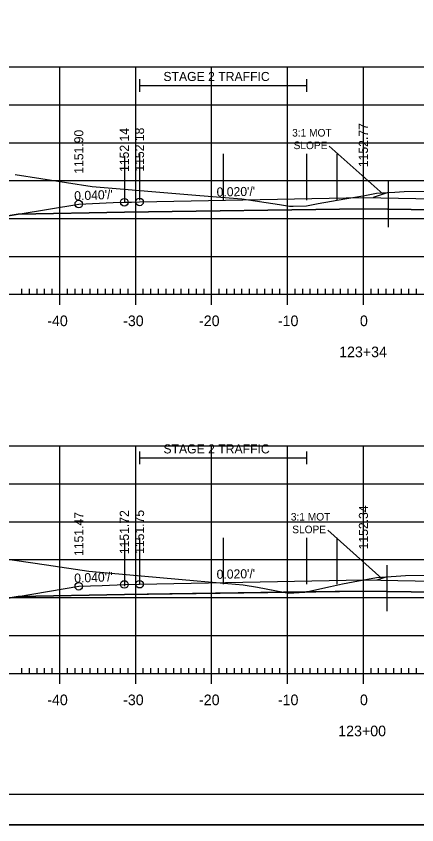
# Model space of a CAD drawing. Extents: x 1322838 to 1324533, y 339903 to 351025.
# Drawn here: x 1323658 to 1323710.8, y 341183.1 to 341289.8 of the extents above; entities that cross this region are included whole.
import ezdxf

# ---------------------------------------------------------------- set-up
doc = ezdxf.new("R2010")
doc.units = 0
for name, color, linetype in [('R_Alt Surface', 7, 'Continuous'), ('R_Axis', 7, 'Continuous'), ('R_Axis Annot', 7, 'Continuous'), ('R_Border', 7, 'Continuous'), ('R_Exist Surface', 7, 'Continuous'), ('R_Fin Surface', 7, 'Continuous'), ('R_Fin Surface Annot', 7, 'Continuous'), ('R_Grid', 7, 'Continuous'), ('R_MOT', 7, 'Continuous'), ('R_No Plot', 7, 'Continuous')]:
    doc.layers.add(name, color=color, linetype=linetype)

msp = doc.modelspace()

# ---------------------------------------------------------------- linework, layer by layer
at = {"layer": 'R_Alt Surface'}
for points in [[(1323658.22, 341263.7), (1323672.22, 341263.98), (1323703.71, 341264.4), (1323735.21, 341263.98), (1323749.21, 341263.7)], [(1323658.22, 341213.27), (1323672.22, 341213.55), (1323703.72, 341213.98), (1323735.22, 341213.55), (1323749.21, 341213.27)]]:
    msp.add_lwpolyline(points, dxfattribs=at)
at = {"layer": 'R_Axis'}
for p, q in [((1323658.72, 341253.13), (1323658.72, 341253.83)), ((1323659.72, 341253.13), (1323659.72, 341253.83)), ((1323660.72, 341253.13), (1323660.72, 341253.83)), ((1323661.72, 341253.13), (1323661.72, 341253.83)), ((1323662.72, 341253.13), (1323662.72, 341253.83)), ((1323663.72, 341251.73), (1323663.72, 341254.53)), ((1323664.72, 341253.13), (1323664.72, 341253.83)), ((1323665.72, 341253.13), (1323665.72, 341253.83)), ((1323666.72, 341253.13), (1323666.72, 341253.83)), ((1323667.72, 341253.13), (1323667.72, 341253.83)), ((1323668.72, 341253.13), (1323668.72, 341253.83)), ((1323669.72, 341253.13), (1323669.72, 341253.83)), ((1323670.72, 341253.13), (1323670.72, 341253.83)), ((1323671.72, 341253.13), (1323671.72, 341253.83)), ((1323672.72, 341253.13), (1323672.72, 341253.83)), ((1323673.72, 341251.73), (1323673.72, 341254.53)), ((1323674.72, 341253.13), (1323674.72, 341253.83)), ((1323675.72, 341253.13), (1323675.72, 341253.83)), ((1323676.72, 341253.13), (1323676.72, 341253.83)), ((1323677.72, 341253.13), (1323677.72, 341253.83)), ((1323678.72, 341253.13), (1323678.72, 341253.83)), ((1323679.72, 341253.13), (1323679.72, 341253.83)), ((1323680.72, 341253.13), (1323680.72, 341253.83)), ((1323681.72, 341253.13), (1323681.72, 341253.83)), ((1323682.72, 341253.13), (1323682.72, 341253.83)), ((1323683.72, 341251.73), (1323683.72, 341254.53)), ((1323684.72, 341253.13), (1323684.72, 341253.83)), ((1323685.72, 341253.13), (1323685.72, 341253.83)), ((1323686.72, 341253.13), (1323686.72, 341253.83)), ((1323687.72, 341253.13), (1323687.72, 341253.83)), ((1323688.72, 341253.13), (1323688.72, 341253.83)), ((1323689.72, 341253.13), (1323689.72, 341253.83)), ((1323690.72, 341253.13), (1323690.72, 341253.83)), ((1323691.72, 341253.13), (1323691.72, 341253.83)), ((1323692.72, 341253.13), (1323692.72, 341253.83)), ((1323693.72, 341251.73), (1323693.72, 341254.53)), ((1323694.72, 341253.13), (1323694.72, 341253.83)), ((1323695.72, 341253.13), (1323695.72, 341253.83)), ((1323696.72, 341253.13), (1323696.72, 341253.83)), ((1323697.72, 341253.13), (1323697.72, 341253.83)), ((1323698.72, 341253.13), (1323698.72, 341253.83)), ((1323699.72, 341253.13), (1323699.72, 341253.83)), ((1323700.72, 341253.13), (1323700.72, 341253.83)), ((1323701.72, 341253.13), (1323701.72, 341253.83)), ((1323702.72, 341253.13), (1323702.72, 341253.83)), ((1323703.72, 341251.73), (1323703.72, 341254.53)), ((1323704.72, 341253.13), (1323704.72, 341253.83)), ((1323705.72, 341253.13), (1323705.72, 341253.83)), ((1323706.72, 341253.13), (1323706.72, 341253.83)), ((1323707.72, 341253.13), (1323707.72, 341253.83)), ((1323708.72, 341253.13), (1323708.72, 341253.83)), ((1323709.72, 341253.13), (1323709.72, 341253.83)), ((1323710.72, 341253.13), (1323710.72, 341253.83)), ((1323563.72, 341253.13), (1323843.72, 341253.13)), ((1323658.72, 341203.13), (1323658.72, 341203.83)), ((1323659.72, 341203.13), (1323659.72, 341203.83)), ((1323660.72, 341203.13), (1323660.72, 341203.83)), ((1323661.72, 341203.13), (1323661.72, 341203.83)), ((1323662.72, 341203.13), (1323662.72, 341203.83)), ((1323663.72, 341201.73), (1323663.72, 341204.53)), ((1323664.72, 341203.13), (1323664.72, 341203.83)), ((1323665.72, 341203.13), (1323665.72, 341203.83)), ((1323666.72, 341203.13), (1323666.72, 341203.83)), ((1323667.72, 341203.13), (1323667.72, 341203.83)), ((1323668.72, 341203.13), (1323668.72, 341203.83)), ((1323669.72, 341203.13), (1323669.72, 341203.83)), ((1323670.72, 341203.13), (1323670.72, 341203.83)), ((1323671.72, 341203.13), (1323671.72, 341203.83)), ((1323672.72, 341203.13), (1323672.72, 341203.83)), ((1323673.72, 341201.73), (1323673.72, 341204.53)), ((1323674.72, 341203.13), (1323674.72, 341203.83)), ((1323675.72, 341203.13), (1323675.72, 341203.83)), ((1323676.72, 341203.13), (1323676.72, 341203.83)), ((1323677.72, 341203.13), (1323677.72, 341203.83)), ((1323678.72, 341203.13), (1323678.72, 341203.83)), ((1323679.72, 341203.13), (1323679.72, 341203.83)), ((1323680.72, 341203.13), (1323680.72, 341203.83)), ((1323681.72, 341203.13), (1323681.72, 341203.83)), ((1323682.72, 341203.13), (1323682.72, 341203.83)), ((1323683.72, 341201.73), (1323683.72, 341204.53)), ((1323684.72, 341203.13), (1323684.72, 341203.83)), ((1323685.72, 341203.13), (1323685.72, 341203.83)), ((1323686.72, 341203.13), (1323686.72, 341203.83)), ((1323687.72, 341203.13), (1323687.72, 341203.83)), ((1323688.72, 341203.13), (1323688.72, 341203.83)), ((1323689.72, 341203.13), (1323689.72, 341203.83)), ((1323690.72, 341203.13), (1323690.72, 341203.83)), ((1323691.72, 341203.13), (1323691.72, 341203.83)), ((1323692.72, 341203.13), (1323692.72, 341203.83)), ((1323693.72, 341201.73), (1323693.72, 341204.53)), ((1323694.72, 341203.13), (1323694.72, 341203.83)), ((1323695.72, 341203.13), (1323695.72, 341203.83)), ((1323696.72, 341203.13), (1323696.72, 341203.83)), ((1323697.72, 341203.13), (1323697.72, 341203.83)), ((1323698.72, 341203.13), (1323698.72, 341203.83)), ((1323699.72, 341203.13), (1323699.72, 341203.83)), ((1323700.72, 341203.13), (1323700.72, 341203.83)), ((1323701.72, 341203.13), (1323701.72, 341203.83)), ((1323702.72, 341203.13), (1323702.72, 341203.83)), ((1323703.72, 341201.73), (1323703.72, 341204.53)), ((1323704.72, 341203.13), (1323704.72, 341203.83)), ((1323705.72, 341203.13), (1323705.72, 341203.83)), ((1323706.72, 341203.13), (1323706.72, 341203.83)), ((1323707.72, 341203.13), (1323707.72, 341203.83)), ((1323708.72, 341203.13), (1323708.72, 341203.83)), ((1323709.72, 341203.13), (1323709.72, 341203.83)), ((1323710.72, 341203.13), (1323710.72, 341203.83)), ((1323563.72, 341203.13), (1323843.72, 341203.13))]:
    msp.add_line(p, q, dxfattribs=at)
at = {"layer": 'R_Axis Annot'}
for p, q in [((1323674.22, 341281.52), (1323674.22, 341279.82)), ((1323696.22, 341281.52), (1323696.22, 341279.82)), ((1323674.22, 341280.67), (1323696.22, 341280.67)), ((1323674.22, 341232.41), (1323674.22, 341230.7)), ((1323674.22, 341231.55), (1323696.22, 341231.55)), ((1323696.22, 341232.41), (1323696.22, 341230.7))]:
    msp.add_line(p, q, dxfattribs=at)
at = {"layer": 'R_Border'}
msp.add_line((1323861.9, 341187.13), (1323545.72, 341187.13), dxfattribs=at)
at = {"layer": 'R_Exist Surface'}
for points in [[(1323657.83, 341268.91), (1323667.97, 341267.35), (1323682.17, 341266.18), (1323687.68, 341265.72), (1323692.67, 341264.96), (1323693.99, 341264.74), (1323694.46, 341264.76), (1323696.22, 341264.8), (1323697.75, 341265.09), (1323701.25, 341265.72), (1323703.92, 341266.18), (1323705.45, 341266.46), (1323707.86, 341266.62), (1323709.1, 341266.7), (1323713.35, 341266.74)], [(1323653.2, 341218.73), (1323661.95, 341217.43), (1323667.55, 341216.59), (1323681.82, 341215.34), (1323687.89, 341214.82), (1323689.75, 341214.49), (1323693.83, 341213.71), (1323695.27, 341213.79), (1323696.02, 341213.83), (1323699.39, 341214.59), (1323700.98, 341214.93), (1323702.37, 341215.19), (1323705.45, 341215.78), (1323708.03, 341215.96), (1323709.28, 341216.04), (1323713.52, 341216.08)]]:
    msp.add_lwpolyline(points, dxfattribs=at)
at = {"layer": 'R_Fin Surface'}
for points in [[(1323613.69, 341271.54), (1323644.22, 341261.37), (1323658.22, 341263.7), (1323658.23, 341263.7), (1323666.22, 341265.03), (1323670.76, 341265.22), (1323672.22, 341265.27), (1323673.18, 341265.29), (1323674.22, 341265.31), (1323703.72, 341265.9), (1323715.25, 341265.67), (1323733.21, 341265.31), (1323733.22, 341265.31), (1323735.22, 341265.27), (1323738.05, 341265.16), (1323741.22, 341265.03), (1323749.21, 341263.7), (1323752.38, 341263.17), (1323763.21, 341261.37), (1323763.22, 341261.37), (1323773.05, 341264.65)], [(1323616.14, 341220.3), (1323644.22, 341210.94), (1323658.22, 341213.27), (1323666.22, 341214.61), (1323669.31, 341214.73), (1323672.22, 341214.85), (1323674.14, 341214.88), (1323674.22, 341214.89), (1323703.72, 341215.48), (1323733.22, 341214.89), (1323734.26, 341214.86), (1323735.22, 341214.85), (1323739.03, 341214.69), (1323741.22, 341214.61), (1323749.21, 341213.27), (1323763.22, 341210.94), (1323766.99, 341212.2), (1323770.21, 341213.27)]]:
    msp.add_lwpolyline(points, dxfattribs=at)
at = {"layer": 'R_Grid'}
for p, q in [((1323563.72, 341283.13), (1323843.72, 341283.13)), ((1323663.72, 341253.13), (1323663.72, 341283.13)), ((1323673.72, 341253.13), (1323673.72, 341283.13)), ((1323683.72, 341253.13), (1323683.72, 341283.13)), ((1323693.72, 341253.13), (1323693.72, 341283.13)), ((1323703.72, 341253.13), (1323703.72, 341283.13)), ((1323563.72, 341278.13), (1323843.72, 341278.13)), ((1323563.72, 341273.13), (1323843.72, 341273.13)), ((1323563.72, 341268.13), (1323843.72, 341268.13)), ((1323563.72, 341263.13), (1323843.72, 341263.13)), ((1323563.72, 341258.13), (1323843.72, 341258.13)), ((1323563.72, 341253.13), (1323843.72, 341253.13)), ((1323563.72, 341233.13), (1323843.72, 341233.13)), ((1323663.72, 341203.13), (1323663.72, 341233.13)), ((1323673.72, 341203.13), (1323673.72, 341233.13)), ((1323683.72, 341203.13), (1323683.72, 341233.13)), ((1323693.72, 341203.13), (1323693.72, 341233.13)), ((1323703.72, 341203.13), (1323703.72, 341233.13)), ((1323563.72, 341228.13), (1323843.72, 341228.13)), ((1323563.72, 341223.13), (1323843.72, 341223.13)), ((1323563.72, 341218.13), (1323843.72, 341218.13)), ((1323563.72, 341213.13), (1323843.72, 341213.13)), ((1323563.72, 341208.13), (1323843.72, 341208.13)), ((1323563.72, 341203.13), (1323843.72, 341203.13))]:
    msp.add_line(p, q, dxfattribs=at)
at = {"layer": 'R_MOT'}
for p, q in [((1323706.32, 341266.32), (1323699.22, 341272.68)), ((1323706.97, 341266.54), (1323704.99, 341265.88)), ((1323706.14, 341215.66), (1323699.04, 341222.02)), ((1323706.79, 341215.87), (1323705.5, 341215.44))]:
    msp.add_line(p, q, dxfattribs=at)
at = {"layer": 'R_No Plot'}
for p, q in [((1323672.22, 341271.38), (1323672.22, 341265.27)), ((1323674.22, 341271.64), (1323674.22, 341265.53)), ((1323685.22, 341271.64), (1323685.22, 341265.53)), ((1323696.22, 341271.64), (1323696.22, 341265.53)), ((1323700.22, 341271.64), (1323700.22, 341265.53)), ((1323706.97, 341268.08), (1323706.97, 341261.98)), ((1323672.22, 341220.74), (1323672.22, 341214.63)), ((1323674.22, 341220.99), (1323674.22, 341214.89)), ((1323685.22, 341220.99), (1323685.22, 341214.89)), ((1323696.22, 341220.99), (1323696.22, 341214.89)), ((1323700.22, 341220.99), (1323700.22, 341214.89)), ((1323706.79, 341217.42), (1323706.79, 341211.31)), ((1323533.31, 341183.15), (1323866.65, 341183.15))]:
    msp.add_line(p, q, dxfattribs=at)
for points in [[(1323533.31, 341396.49), (1323866.65, 341396.49), (1323866.65, 341183.15), (1323533.31, 341183.15)], [(1323779.64, 341392.59), (1323799.26, 341392.59), (1323799.26, 341382.71), (1323815.37, 341382.71), (1323838.57, 341382.71), (1323838.57, 341350.04), (1323861.77, 341350.04), (1323861.9, 341187.13), (1323545.72, 341187.13), (1323545.72, 341392.59)], [(1323616.14, 341220.3), (1323653.2, 341218.73), (1323661.95, 341217.43), (1323667.55, 341216.59), (1323681.82, 341215.34), (1323687.89, 341214.82), (1323689.75, 341214.49), (1323693.19, 341213.83), (1323672.22, 341213.55), (1323658.22, 341213.27), (1323644.22, 341210.94), (1323616.14, 341220.3)], [(1323693.19, 341213.83), (1323693.83, 341213.71), (1323695.27, 341213.79), (1323696.02, 341213.83), (1323696.23, 341213.88)]]:
    msp.add_lwpolyline(points, close=True, dxfattribs=at)
for points in [[(1323657.83, 341268.91), (1323667.97, 341267.35), (1323682.17, 341266.18), (1323687.68, 341265.72), (1323692.67, 341264.96), (1323693.99, 341264.74), (1323694.46, 341264.76), (1323696.22, 341264.8), (1323697.75, 341265.09), (1323701.25, 341265.72), (1323703.92, 341266.18), (1323705.45, 341266.46), (1323707.86, 341266.62), (1323709.1, 341266.7), (1323713.35, 341266.74)], [(1323735.21, 341263.98), (1323703.71, 341264.4), (1323672.22, 341263.98), (1323658.22, 341263.7), (1323644.22, 341261.37)], [(1323735.22, 341213.55), (1323703.72, 341213.98), (1323696.23, 341213.88), (1323699.39, 341214.59), (1323700.98, 341214.93), (1323702.37, 341215.19), (1323705.45, 341215.78), (1323708.03, 341215.96), (1323709.28, 341216.04), (1323713.52, 341216.08)]]:
    msp.add_lwpolyline(points, dxfattribs=at)
for centre in [(1323666.22, 341265.03), (1323666.22, 341265.03), (1323672.22, 341265.27), (1323672.22, 341265.27), (1323674.22, 341265.31), (1323674.22, 341265.31), (1323674.22, 341214.89), (1323674.22, 341214.89), (1323666.22, 341214.61), (1323666.22, 341214.61), (1323672.22, 341214.85), (1323672.22, 341214.85)]:
    msp.add_circle(centre, 0.5, dxfattribs=at)

# ---------------------------------------------------------------- texts
at = {"layer": 'R_Axis Annot'}
for s, height, p in [('STAGE 2 TRAFFIC', 1.2, (1323677.37, 341281.26)), ('-40', 1.4, (1323662.06, 341248.93)), ('-30', 1.4, (1323672.06, 341248.93)), ('-20', 1.4, (1323682.06, 341248.93)), ('-10', 1.4, (1323692.45, 341248.93)), ('0', 1.4, (1323703.26, 341248.93)), ('123+34', 1.4, (1323700.52, 341244.83)), ('STAGE 2 TRAFFIC', 1.2, (1323677.37, 341232.14)), ('-40', 1.4, (1323662.06, 341198.93)), ('-30', 1.4, (1323672.06, 341198.93)), ('-20', 1.4, (1323682.06, 341198.93)), ('-10', 1.4, (1323692.45, 341198.93)), ('0', 1.4, (1323703.26, 341198.93)), ('123+00', 1.4, (1323700.4, 341194.83))]:
    msp.add_text(s, height=height, dxfattribs=at).set_placement(p)
at = {"layer": 'R_Fin Surface Annot'}
for s, rotation, p in [('1152.77', 90, (1323704.31, 341269.9)), ('1151.90', 90, (1323666.82, 341269.03)), ('1152.14', 90, (1323672.82, 341269.27)), ('1152.18', 90, (1323674.82, 341269.31)), ("0.040'/'", 2.2906, (1323665.64, 341265.51)), ("0.020'/'", 1.1458, (1323684.39, 341266.02)), ('1152.34', 90, (1323704.32, 341219.48)), ('1151.47', 90, (1323666.82, 341218.61)), ('1151.72', 90, (1323672.82, 341218.85)), ('1151.75', 90, (1323674.82, 341218.89)), ("0.040'/'", 2.2907, (1323665.64, 341215.08)), ("0.020'/'", 1.1457, (1323684.39, 341215.59))]:
    msp.add_text(s, height=1.2, rotation=rotation, dxfattribs=at).set_placement(p)
at = {"layer": 'R_MOT'}
for s, p in [('3:1 MOT', (1323694.33, 341273.94)), ('SLOPE', (1323694.52, 341272.28)), ('3:1 MOT', (1323694.16, 341223.28)), ('SLOPE', (1323694.34, 341221.61))]:
    msp.add_text(s, height=1, dxfattribs=at).set_placement(p)

doc.saveas('drawing.dxf')
